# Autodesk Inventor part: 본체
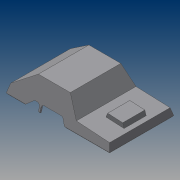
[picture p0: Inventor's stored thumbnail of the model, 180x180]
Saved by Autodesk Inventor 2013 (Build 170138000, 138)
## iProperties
Created: 2015-05
Part Number: 본체
Material: 일반
Document SubType Name: Modeling
Designer: Administrator
Density: 1 g/cm^3
Author: Administrator
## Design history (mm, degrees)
sketch "스케치1"
  geometry: L1 (-61, 38)-(61, 38); L2 (61, 38)-(61, -38); L3 (61, -38)-(-61, -38); L4 (-61, -38)-(-61, 38); L5 (-61, 38)-(61, -38); L6 (61, 38)-(-61, -38); 1 further point
  constraints: 12 end point, 2 midpoint, 2 parallel, 1 horizontal, 1 perpendicular
  dimensions: "d0" = 122 distance of L2.end L3.end; "d1" = 76 distance of L1.end L2.end
extrude "돌출1" new body sketch "스케치1" distance "d2" = 31; taper "d3" = -15 deg
sketch "스케치5"
  geometry: L1 (-52.694, 31)-(52.694, 31) reference; L2 (61, 0)-(52.694, 31) reference; L3 (-61, 0)-(61, 0) reference; L4 (-61, 0)-(-52.694, 31) reference; L5 (-61, 0)-(-52.694, 31); L6 (52.694, 31)-(61, 0); L7 (-52.694, 31)-(52.694, 31); L8 (-61, 0)-(61, 0); L9 (-58.588, 9)-(-19, 11.075); L10 (-6.549, 31)-(-19, 11.075); L11 (31, 31)-(58.053, 11); 1 further point
  constraints: 14 end point, 4 point on line, 2 collinear, 2 parallel
  dimensions: "d46" = 20 distance from line of L11.end L1; "d47" = 42 horizontal distance of L9.end L3.start; "d48" = 125 deg angle of L9 L10; "d49" = 3 deg angle of L3 L9; "d50" = 9 vertical distance of L3.start L9.start; "d70" = 30 horizontal distance of L11.start L2.start
  node "투영된 루프4"
extrude "돌출4" cut sketch "스케치5" stored distance "d51" = 76; taper "d52" = 0 deg
extrude "돌출5" cut sketch "스케치5" stored distance "d53" = 76; taper "d54" = 0 deg
sketch "스케치7"
  geometry: L1 (-51.439, 14.382)-(-33.819, 15.305); L2 (-52.995, 9.293)-(-51.439, 14.382); L3 (-33.819, 15.305)-(-31.74, 10.407); L4 (-58.588, 9)-(-19, 11.075) reference; L5 (-61, 0)-(-52.694, 31) reference; L6 (-52.694, 9.309)-(-31.74, 10.407); 1 further point
  constraints: 8 end point, 3 point on line, 1 collinear, 1 parallel
  dimensions: "d55" = 5 distance from line of L1 L4.start; "d56" = 70 deg angle of L4 L2; "d57" = 70 deg angle of L4 L3; "d58" = 20 distance from line of L2.start L3; "d59" = 31 distance from line of L5.start L3
extrude "돌출6" join sketch "스케치7" stored distance "d60" = 26; taper "d61" = 0 deg
feature "쉘1" dims "d62" = 2
sketch "스케치9"
  geometry: L1 (61, 38)-(-61, 38) reference; L2 (-61, 38)-(-61, -38) reference; L3 (-61, -38)-(61, -38) reference; L4 (61, -38)-(61, 38) reference; L5 (-60, 37)-(60, 37); L6 (60, 37)-(60, -37); L7 (60, -37)-(-60, -37); L8 (-60, -37)-(-60, 37); 1 further point
  constraints: 8 end point, 3 other
  dimensions: "d84" = 1 distance between parallel lines of L1 L5
extrude "돌출7" cut sketch "스케치9" distance "d85" = 1; taper "d86" = 0 deg
sketch "스케치10"
  geometry: L1 (91.732, 31.058)-(-29.732, 31.058) reference; L2 (-27.053, 20.706)-(0, 0) reference; L3 (0, 0)-(37.549, 0) reference; L4 (37.549, 0)-(50, 20.628) reference; L5 (91.732, 31.058)-(89.588, 22.776) reference; L6 (1.694, 5)-(-10.872, 14.618); L7 (85.273, 26.058)-(85.665, 27.571); L8 (41.034, 15.45)-(35.602, 6.45); L9 (9.781, 8)-(9.781, 17); L10 (8.096, 8)-(8.096, 17); L11 (33.034, 5)-(12.781, 5); L12 (5.096, 5)-(1.694, 5); L13 (38.466, 20)-(12.781, 20); L14 (5.096, 20)-(-9.049, 20); A1 r 3 centre (33.034, 8) between (33.034, 5) and (35.602, 6.45); A2 r 3 centre (38.466, 17) between (41.034, 15.45) and (38.466, 20); A3 r 3 centre (12.781, 17) between (12.781, 20) and (9.781, 17); A4 r 3 centre (12.781, 8) between (9.781, 8) and (12.781, 5); A5 r 3 centre (5.096, 8) between (5.096, 5) and (8.096, 8); A6 r 3 centre (5.096, 17) between (8.096, 17) and (5.096, 20); A7 r 3 centre (-9.049, 17) between (-9.049, 20) and (-10.872, 14.618); 5 further points
  constraints: 18 end point, 16 tangent, 14 point on circle, 8 point on line, 7 centre point, 7 parallel, 6 equal radius, 2 perpendicular
  dimensions: "d94" = 5 distance between parallel lines of L2 L6; "d96" = 5 distance between parallel lines of L8 L4; "d98" = 34 distance of point (43.781, 20) point (9.781, 20); "d99" = 26 distance of point (8.096, 20) point (-17.904, 20); "d101" = 15 distance between parallel lines of L14 L12; "d103" = 3 radius of A1; "d104" = 11.05829 distance between parallel lines of L1 L13; "d105" = 5 distance between parallel lines of L7 L5; "d106" = 3.48775 distance from line of L7.end L1; "d107" = 5 distance from line of L7.start L1
extrude "돌출8" cut sketch "스케치10" distance "d108" = 76; taper "d109" = 0 deg
node "솔리드1"
other parameters: "d63" = 5, "d65" = 15, "d75" = 5, "d76" = 15, "d97" = 5 (derived)
